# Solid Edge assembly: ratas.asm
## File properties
Title: Ratas
Author: Romil
Template: iso assembly.asm
Last saved by: Romil
Revision: 8
Application: Solid Edge
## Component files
velg.par
kumm.par
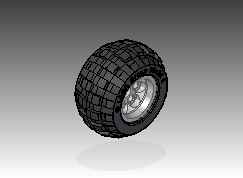
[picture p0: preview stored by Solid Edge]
